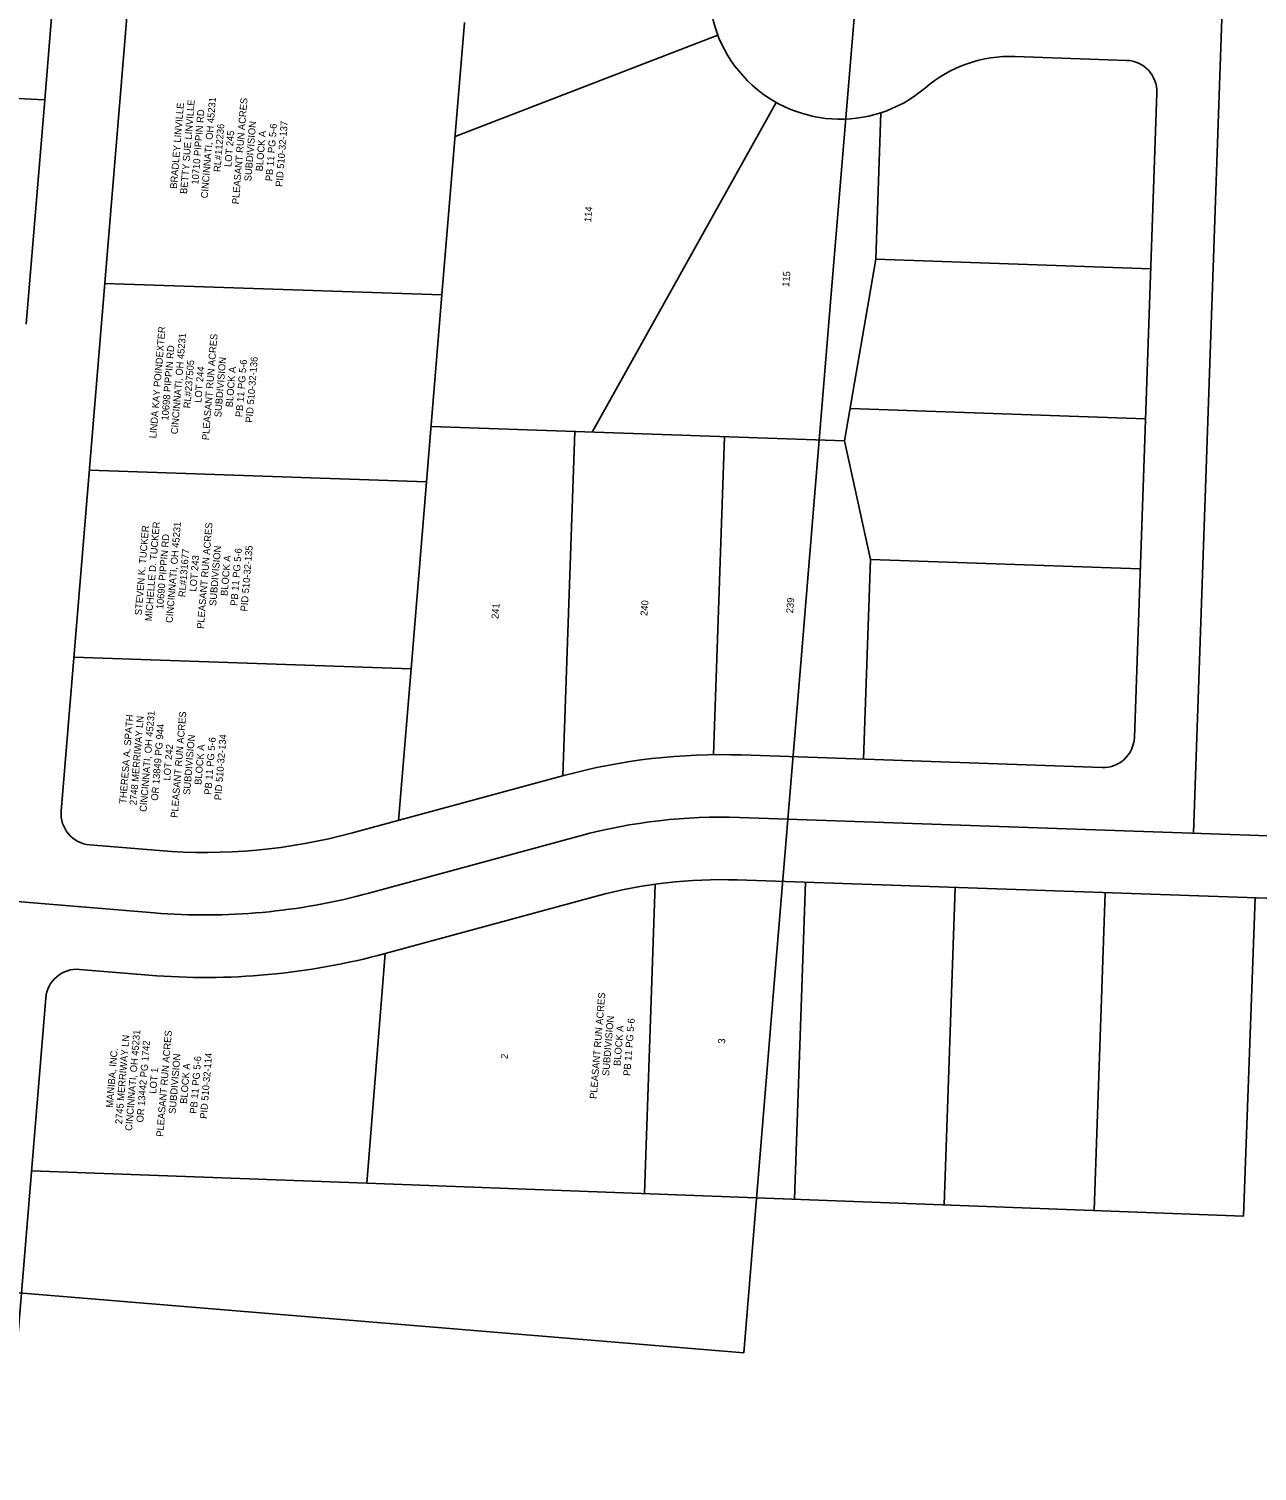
# Model space of a CAD drawing. Extents: x 1379776 to 1382941, y 467490 to 471592.
# Drawn here: x 1381551 to 1382042, y 468925 to 469502 of the extents above; entities that cross this region are included whole.
import ezdxf

# ---------------------------------------------------------------- set-up
doc = ezdxf.new("R2010")
doc.units = 0
for name, color, linetype in [('DR_X_Text', 7, 'Continuous'), ('PV_P_Drive', 7, 'Continuous'), ('RC_X_Text', 7, 'Continuous'), ('RD_X_Wall', 7, 'Continuous'), ('SH_Named_Boundary', 7, 'Continuous'), ('SV_X_Break_Lines', 7, 'Continuous')]:
    doc.layers.add(name, color=color, linetype=linetype)

msp = doc.modelspace()

# ---------------------------------------------------------------- linework, layer by layer
at = {"layer": 'DR_X_Text'}
for p, q in [((1381835.11, 469186.42), (1382054.46, 469178.8)), ((1381686.85, 469156.13), (1381771.4, 469179.06)), ((1381530.8, 469154.06), (1381600.93, 469148.27))]:
    msp.add_line(p, q, dxfattribs=at)
msp.add_lwpolyline([(1382016.8, 469180.11), (1382043.72, 469954.66), (1382306.88, 469945.51)], dxfattribs=at)
for centre, radius, start, end in [((1381827.64, 468971.69), 214.86, 88.00942, 105.17609), ((1381621.49, 469397.09), 249.67, 265.27609, 285.17609)]:
    msp.add_arc(centre, radius, start, end, dxfattribs=at)
at = {"layer": 'PV_P_Drive'}
for p, q in [((1381564.61, 469563.17), (1381557.19, 469473.48)), ((1381725.12, 469504.34), (1381716.12, 469395.42)), ((1381073.36, 469495.51), (1381557.19, 469473.48)), ((1381557.19, 469473.48), (1381549.78, 469383.79)), ((1381581.23, 469400.05), (1381716.12, 469395.42)), ((1381716.12, 469395.42), (1381709.94, 469320.67)), ((1381709.94, 469320.67), (1381575.05, 469325.31)), ((1381709.94, 469320.67), (1381703.77, 469245.93)), ((1381703.77, 469245.93), (1381568.87, 469250.56)), ((1381698.75, 469185.26), (1381703.77, 469245.93)), ((1381693.4, 469132.07), (1381686, 469040.12)), ((1381686, 469040.12), (1381551.9, 469045.13))]:
    msp.add_line(p, q, dxfattribs=at)
msp.add_lwpolyline([(1381686, 469040.12), (1382036.77, 469027), (1382041.37, 469154.24)], dxfattribs=at)
at = {"layer": 'RD_X_Wall'}
for p, q in [((1381563.78, 469188.96), (1381609.99, 469748.14)), ((1381945.39, 469490.77), (1381990.02, 469489.22)), ((1382002.08, 469476.3), (1381993.11, 469218.45)), ((1381980.19, 469206.39), (1381835.98, 469211.41)), ((1381764.85, 469203.19), (1381680.31, 469180.25)), ((1381602.99, 469173.18), (1381575.21, 469175.48)), ((1381693.4, 469132), (1381777.94, 469154.93)), ((1381571.1, 469125.65), (1381598.87, 469123.35)), ((1381541.97, 468924.96), (1381557.61, 469114.22))]:
    msp.add_line(p, q, dxfattribs=at)
msp.add_lwpolyline([(1381834.24, 469161.44), (1382053.59, 469153.81), (1382055.33, 469203.78), (1382055.14, 469203.79)], dxfattribs=at)
for centre, radius, start, end in [((1381875.46, 469518.22), 52.5, 45.57884, 310.44001), ((1381943.56, 469438.31), 52.5, 88.00942, 130.44001), ((1381989.58, 469476.73), 12.5, 358.00942, 88.00942), ((1381980.62, 469218.89), 12.5, 268.00942, 358.00942), ((1381827.64, 468971.69), 239.86, 88.00942, 105.17609), ((1381576.24, 469187.93), 12.5, 175.27613, 265.27609), ((1381621.49, 469397.09), 224.67, 265.27609, 285.17609), ((1381827.64, 468971.69), 189.86, 88.00942, 105.17609), ((1381621.49, 469397.09), 274.67, 265.27609, 285.17609), ((1381570.07, 469113.19), 12.5, 85.27609, 175.27692)]:
    msp.add_arc(centre, radius, start, end, dxfattribs=at)
at = {"layer": 'SH_Named_Boundary'}
msp.add_lwpolyline([(1381019.66, 469039.84), (1381836.87, 468972.31), (1381848.4, 469111.83), (1381859.93, 469251.36), (1381871.46, 469390.88), (1381882.99, 469530.4), (1381894.52, 469669.93), (1381906.05, 469809.45), (1381917.58, 469948.98), (1381929.11, 470088.5), (1381940.64, 470228.03), (1381952.16, 470367.55), (1381134.95, 470435.08), (1381123.42, 470295.56), (1381111.89, 470156.03), (1381100.36, 470016.51), (1381088.83, 469876.98), (1381077.3, 469737.46), (1381065.77, 469597.93), (1381054.24, 469458.41), (1381042.71, 469318.88), (1381031.19, 469179.36)], close=True, dxfattribs=at)
at = {"layer": 'SV_X_Break_Lines'}
for p, q in [((1381721.36, 469458.84), (1381826.47, 469499.34)), ((1381776.22, 469340.58), (1381849.85, 469472.39)), ((1381889.69, 469409.66), (1381891.73, 469468.31)), ((1381877.16, 469337.07), (1381889.69, 469409.66)), ((1381999.63, 469405.84), (1381889.69, 469409.66)), ((1381997.54, 469345.88), (1381879.39, 469349.98)), ((1381877.16, 469337.07), (1381711.77, 469342.82)), ((1381764.42, 469203.07), (1381769.21, 469340.83)), ((1381824.75, 469211.53), (1381829.17, 469338.74)), ((1381887.52, 469289.66), (1381877.16, 469337.07)), ((1381887.52, 469289.66), (1381884.75, 469209.71)), ((1381995.46, 469285.91), (1381887.52, 469289.66)), ((1381797.08, 469035.96), (1381801.38, 469159.73)), ((1381857.08, 469033.72), (1381861.48, 469160.49)), ((1381917.03, 469031.48), (1381921.45, 469158.41)), ((1381976.99, 469029.24), (1381981.41, 469156.32))]:
    msp.add_line(p, q, dxfattribs=at)

# ---------------------------------------------------------------- texts
at = {"layer": 'RC_X_Text'}
for s, p in [('BETTY SUE LINVILLE', (1381614.11, 469435.71)), ('CINCINNATI, OH 45231', (1381622.39, 469433.96)), ('PLEASANT RUN ACRES', (1381634.84, 469431.61)), ('BRADLEY LINVILLE', (1381610.06, 469437.79)), ('10710 PIPPIN RD', (1381618.63, 469439.45)), ('RL#112236', (1381627.48, 469444.49)), ('SUBDIVISION', (1381639.81, 469440.78)), ('PB 11 PG 5-6', (1381648.24, 469440.81)), ('PID 510-32-137', (1381652.27, 469438.54)), ('LOT 245', (1381631.85, 469446.49)), ('BLOCK A', (1381644.36, 469444.78)), ('114', (1381775.78, 469424.45)), ('115', (1381854.98, 469398.56)), ('LINDA KAY POINDEXTER', (1381601.82, 469337.96)), ('10698 PIPPIN RD', (1381606.62, 469345.09)), ('CINCINNATI, OH 45231', (1381610.38, 469339.61)), ('PLEASANT RUN ACRES', (1381622.83, 469337.25)), ('SUBDIVISION', (1381627.8, 469346.42)), ('PB 11 PG 5-6', (1381636.23, 469346.46)), ('PID 510-32-136', (1381640.26, 469344.23)), ('RL#237505', (1381615.45, 469349.98)), ('LOT 244', (1381619.85, 469352.18)), ('BLOCK A', (1381632.35, 469350.43)), ('STEVEN K. TUCKER', (1381595.97, 469267.23)), ('MICHELLE D. TUCKER', (1381599.99, 469264.83)), ('CINCINNATI, OH 45231', (1381608.36, 469264.13)), ('PLEASANT RUN ACRES', (1381620.81, 469261.77)), ('10690 PIPPIN RD', (1381604.6, 469269.61)), ('SUBDIVISION', (1381625.78, 469270.94)), ('PID 510-32-135', (1381638.24, 469268.74)), ('RL#131677', (1381613.43, 469274.45)), ('LOT 243', (1381617.82, 469276.68)), ('BLOCK A', (1381630.32, 469274.94)), ('PB 11 PG 5-6', (1381634.21, 469270.98)), ('241', (1381738.68, 469265.71)), ('240', (1381798.26, 469266.96)), ('239', (1381856.55, 469267.97)), ('THERESA A. SPATH', (1381589.74, 469191.8)), ('2748 MERRIWAY LN', (1381593.91, 469191.25)), ('CINCINNATI, OH 45231', (1381597.9, 469188.55)), ('PLEASANT RUN ACRES', (1381610.35, 469186.2)), ('OR 13849 PG 944', (1381602.48, 469193.02)), ('PID 510-32-134', (1381627.78, 469193.23)), ('LOT 242', (1381607.36, 469201.09)), ('SUBDIVISION', (1381615.32, 469195.37)), ('BLOCK A', (1381619.86, 469199.37)), ('PB 11 PG 5-6', (1381623.75, 469195.4)), ('PLEASANT RUN ACRES', (1381777.97, 469073.76)), ('SUBDIVISION', (1381782.95, 469082.93)), ('PB 11 PG 5-6', (1381791.38, 469082.97)), ('2745 MERRIWAY LN', (1381588.13, 469063.67)), ('CINCINNATI, OH 45231', (1381592.12, 469060.98)), ('PLEASANT RUN ACRES', (1381604.57, 469058.62)), ('BLOCK A', (1381787.49, 469086.94)), ('MANIBA, INC.', (1381584.45, 469070.23)), ('OR 13442 PG 1742', (1381596.61, 469064.33)), ('3', (1381829.33, 469095.82)), ('SUBDIVISION', (1381609.54, 469067.79)), ('BLOCK A', (1381614.08, 469071.79)), ('PB 11 PG 5-6', (1381617.97, 469067.83)), ('PID 510-32-114', (1381622.02, 469065.79)), ('2', (1381742.4, 469089.72)), ('LOT 1', (1381601.77, 469075.85))]:
    msp.add_text(s, height=2.8, rotation=85.27618, dxfattribs=at).set_placement(p)

doc.saveas('drawing.dxf')
